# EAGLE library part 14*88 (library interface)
Quad 2-input NAND gate
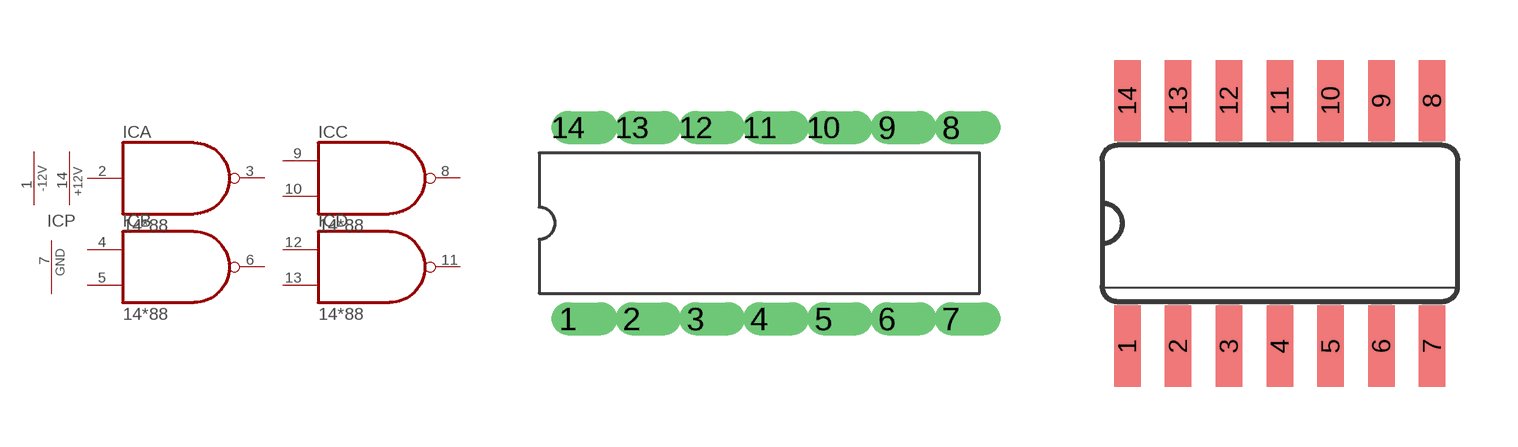
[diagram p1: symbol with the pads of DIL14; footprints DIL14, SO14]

Designator prefix IC; gates A=1488A B=1488 C=1488 D=1488 P=2PWR1GND

## 1488N, 14C88N  [DIL14]
1  P:-12V  pwr
2  A:I  in
3  A:O  out
4  B:I0  in
5  B:I1  in
6  B:O  out
7  P:GND  pwr
8  C:O  out
9  C:I0  in
10  C:I1  in
11  D:O  out
12  D:I0  in
13  D:I1  in
14  P:+12V  pwr

## 1488D, 14C88D  [SO14]
Pads as for DIL14

## Footprint DIL14 (pad centres in mm)
Dual In Line 14
drill 0.8 offset: 1 -7.62,-3.81; 2 -5.08,-3.81; 3 -2.54,-3.81; 4 0,-3.81; 5 2.54,-3.81; 6 5.08,-3.81; 7 7.62,-3.81; 8 7.62,3.81; 9 5.08,3.81; 10 2.54,3.81; 11 0,3.81; 12 -2.54,3.81; 13 -5.08,3.81; 14 -7.62,3.81

## Footprint SO14 (pad centres in mm)
SO14 Small Outline package, 150 mil
smd 0.66 x 2.032: 1 -3.81,-3.073; 2 -2.54,-3.073; 3 -1.27,-3.073; 4 0,-3.073; 5 1.27,-3.073; 6 2.54,-3.073; 7 3.81,-3.073; 8 3.81,3.073; 9 2.54,3.073; 10 1.27,3.073; 11 0,3.073; 12 -1.27,3.073; 13 -2.54,3.073; 14 -3.81,3.073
